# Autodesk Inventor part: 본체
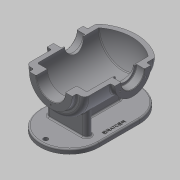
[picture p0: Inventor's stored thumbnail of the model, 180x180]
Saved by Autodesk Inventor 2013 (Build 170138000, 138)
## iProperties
Created: 2016-02
Part Number: 본체
Material: 일반
Document SubType Name: Modeling
Designer: mduedu
Density: 2.71 g/cm^3
Mass: 2160.69 g
Surface Area: 1522.29 cm^2
Volume: 797.301 cm^3
Author: mduedu
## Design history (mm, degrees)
sketch "스케치2"
  geometry: L1 (0, 90)-(0, -90); L2 (65, -65.993)-(65, 90); L3 (65, 90)-(0, 90); A1 r 100 centre (0, 10) between (0, -90) and (65, -65.993); 2 further points
  constraints: 6 end point, 2 point on circle, 1 centre point, 1 coincident, 1 horizontal, 1 midpoint, 1 parallel, 1 point on line, 1 vertical
  dimensions: "d3" = 180 distance of L1.start L1.end; "d5" = 130 diameter of L2 L1; "d6" = 100 radius of A1
revolve "회전1" sketch "스케치2" stored, may be unused: angle "d7" = 90 deg
sketch "스케치3"
  geometry: C1 r 47.5 at (0, 0); 1 further point
  constraints: 1 centre point, 1 coincident
  dimensions: "d8" = 95 diameter of C1
extrude "돌출2" join sketch "스케치3" distance "d10" = 10; taper "d11" = 0 deg
sketch "스케치5"
  geometry: L1 (47.5, 100)-(47.5, 90) reference; L2 (47.5, 90)-(65, 90) reference; L3 (65, 90)-(65, -65.993) reference; L4 (-65, -65.993)-(-65, 90) reference; L5 (-65, 90)-(-47.5, 90) reference; L6 (-47.5, 90)-(-47.5, 100) reference; L7 (-47.5, 100)-(47.5, 100) reference; L8 (55, 75)-(55, -61.239); L9 (0, 75)-(55, 75); L10 (0, 75)-(0, -80); A1 r 100 centre (0, 10) between (-65, -65.993) and (0, -90) reference; A2 r 100 centre (0, 10) between (0, -90) and (65, -65.993) reference; A3 r 90 centre (0, 10) between (0, -80) and (55, -61.239); 1 further point
  constraints: 6 end point, 2 point on circle, 1 centre point, 1 parallel, 1 perpendicular, 1 point on line, 1 vertical
  dimensions: "d13" = 10 distance between parallel lines of L3 L8; "d14" = 10 radial gap between concentric circles of A3 A1; "d15" = 15 distance between parallel lines of L9 L2
revolve "회전2" sketch "스케치5" stored, may be unused: angle "d16" = 90 deg
hole "구멍1" diameter "d19" = 65; stored, may be unused: countersink angle "d23" = 90 deg, drill point angle "d25" = 118 deg; dims "d17" = 10, "d18" = 10, "d20" = 6, "d21" = 4, "d22" = 2, "d24" = 8
node "작업 평면1"
sketch "스케치6"
  geometry: L1 (47.5, 100)-(-47.5, 100) reference; C1 r 40 at (0, -7); 1 further point
  constraints: 1 centre point, 1 vertical alignment
  dimensions: "d27" = 80 diameter of C1; "d29" = 107 distance from line of C1.centre L1
extrude "돌출3" join sketch "스케치6" stored distance "d30" = 10; taper "d31" = 0 deg
hole "구멍2" diameter "d34" = 42; stored, may be unused: countersink angle "d38" = 90 deg, drill point angle "d40" = 118 deg; dims "d32" = 10, "d33" = 10, "d35" = 6, "d36" = 52, "d37" = 18, "d39" = 8
sketch "스케치7" dims "d41" = 65
  geometry: C1 r 40 at (0, 0) reference; 3 further points
  constraints: 2 vertical alignment, 1 coincident, 2 other
hole "구멍3" sketch "스케치7" at (0, 32.5) diameter "d43" = 3.242; stored, may be unused: countersink angle "d47" = 90 deg, drill point angle "d49" = 118 deg; dims "d44" = 11, "d45" = 13, "d46" = 18, "d48" = 13
sketch "스케치8" dims "d53" = 80
  geometry: 3 further points
  constraints: 2 vertical alignment, 1 coincident, 2 other
hole "구멍4" sketch "스케치8" at (0, -40) diameter "d56" = 3.242; stored, may be unused: countersink angle "d60" = 90 deg, drill point angle "d62" = 118 deg; dims "d57" = 11, "d58" = 13, "d59" = 18, "d61" = 13
fillet "모깎기1" dims "d66" = 10
fillet "모깎기2" dims "d67" = 3
fillet "모깎기3" dims "d68" = 1
chamfer "모따기1" distance "d69" = 1; stored, may be unused: second distance "d70" = 2, angle "d71" = 45 deg
node "작업 평면5"
sketch "스케치10"
  geometry: L1 (-45, 66)-(45, 66); L2 (45, 66)-(45, 50); L3 (45, 50)-(-45, 50); L4 (-45, 50)-(-45, 66); 2 further points
  constraints: 8 end point, 2 horizontal, 2 vertical, 1 midpoint, 1 vertical alignment
  dimensions: "d177" = 50 distance from line of L3 point (0, 0); "d178" = 90 distance of L1.start L1.end; "d179" = 16 distance of L3.end L1.start
extrude "돌출5" join sketch "스케치10" stored distance "d84" = 10; taper "d85" = 0 deg
sketch "스케치21" dims "d180" = 220, "d182" = 130
  geometry: L1 (65, 58)-(-65, 58); L2 (-65, 58)-(-65, -32); L3 (-65, -32)-(65, -32); L4 (65, -32)-(65, 58); L5 (45, 50)-(45, 66) reference; 4 further points
  constraints: 8 end point, 3 horizontal alignment, 3 midpoint, 2 parallel, 1 horizontal, 1 perpendicular, 1 vertical alignment, 4 other
extrude "돌출13" join sketch "스케치21" distance "d183" = 10; taper "d184" = 0 deg
sketch "스케치11"
  geometry: L1 (-65, 80)-(-65, -61.239) reference; L2 (-100, -97)-(-100, -32) reference; L3 (-65, -45.829)-(-100, -52); L4 (-100, -97)-(-110, -97) reference; 1 further point
  constraints: 2 end point, 2 point on line
  dimensions: "d185" = 45 distance from line of L3.end L4; "d186" = 100 deg angle of L2 L3
feature "리브1" sketch "스케치11" dims "d88" = 1, "d89" = 16, "d90" = 0, "d91" = 0, "d92" = 1, "d93" = 1
fillet "모깎기12"
fillet "모깎기13"
fillet "모깎기16" dims "d167" = 3
fillet "모깎기18"
fillet "모깎기17" dims "d168" = 3
fillet "모깎기19" dims "d187" = 3
node "작업 평면6"
sketch "스케치19"
  geometry: L1 (75, -47)-(75, 33) reference; L2 (-75, -47)-(-75, 33) reference; L3 (75, -7)-(-75, -7); C1 r 22.5 at (0, -7); 1 further point
  constraints: 3 midpoint, 2 end point, 1 centre point
  dimensions: "d149" = 45 diameter of C1
extrude "돌출11" join sketch "스케치19" stored distance "d150" = 10; taper "d151" = 0 deg
hole "구멍6" diameter "d154" = 33.376; stored, may be unused: countersink angle "d158" = 90 deg, drill point angle "d160" = 118 deg; dims "d155" = 6, "d156" = 4, "d157" = 2, "d159" = 8, "d190" = 10, "d191" = 10
fillet "모깎기11" dims "d161" = 3
chamfer "모따기3" distance "d164" = 1; stored, may be unused: second distance "d165" = 2, angle "d166" = 45 deg
node "작업 평면9"
  node "작업 평면8"
sketch "스케치22"
  geometry: L1 (-65, -58)-(-65, 32) reference; L2 (65, 32)-(65, -58) reference; L3 (53, 32)-(53, -58); L4 (-53, -58)-(-53, 32); C1 r 5 at (0, -111); A1 r 65 centre (0, -58) between (-65, -58) and (65, -58) reference; A2 r 65 centre (0, 32) between (65, 32) and (-65, 32) reference; A3 r 53 centre (0, 32) between (53, 32) and (-53, 32); A4 r 53 centre (0, -58) between (-53, -58) and (53, -58); 1 further point
  constraints: 5 point on circle, 4 end point, 3 centre point, 3 other
  dimensions: "d201" = 12 distance between parallel lines of L3 L2; "d202" = 10 diameter of C1
extrude "돌출14" cut sketch "스케치22" stored distance "d194" = 10; taper "d195" = 0 deg
fillet "모깎기21" dims "d196" = 3
feature "분할1"
sketch "스케치23"
  geometry: L1 (-65, 32)-(-65, -58) reference; L2 (65, -58)-(65, 32) reference; L3 (-65, -13)-(65, -13); 2 further points
  constraints: 2 end point, 2 midpoint, 1 point on line, 1 other
  dimensions: "d197" = 12 distance from line of point (53, -13) L2
feature "엠보싱2" sketch "스케치23" dims "d8" = 95, "d198" = 0.5, "d199" = 0
node "솔리드2"
pattern_circular "원형 패턴1" dims angle "d51" = 360 deg
mirror "대칭1"
pattern_circular "원형 패턴2" dims angle "d64" = 360 deg
mirror "대칭3"
node "절단 모서리 투영1"
other parameters: "d26" = 75, "d136" = 175
